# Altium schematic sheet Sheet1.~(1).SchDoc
size A
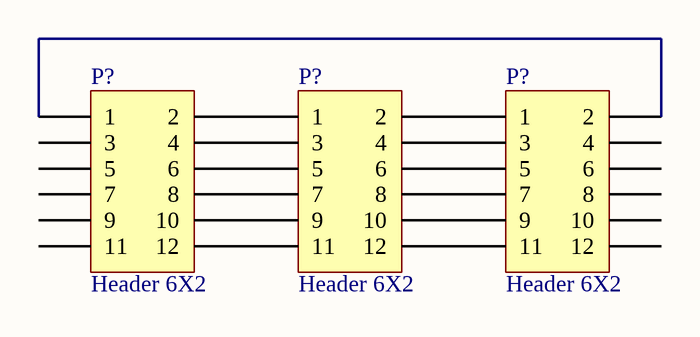
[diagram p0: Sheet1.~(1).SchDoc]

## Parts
(Parts that share a designator on the sheet are numbered #1, #2 ... from top to bottom, then left to right.)
P?#1  Header 6X2  [HDR2X6]
P?#2  Header 6X2  [HDR2X6]
P?#3  Header 6X2  [HDR2X6]

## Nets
NetP?#1_1: P?#1.1 P?#3.2
NetP?#1_2: P?#1.2 P?#2.1
NetP?#1_4: P?#1.4 P?#2.3
NetP?#1_6: P?#1.6 P?#2.5
NetP?#1_8: P?#1.8 P?#2.7
NetP?#1_10: P?#1.10 P?#2.9
NetP?#1_12: P?#1.12 P?#2.11
NetP?#2_2: P?#2.2 P?#3.1
NetP?#2_4: P?#2.4 P?#3.3
NetP?#2_6: P?#2.6 P?#3.5
NetP?#2_8: P?#2.8 P?#3.7
NetP?#2_10: P?#2.10 P?#3.9
NetP?#2_12: P?#2.12 P?#3.11

Not connected (* = marked no-connect by the designer): P?#1 3 5 7 9 11; P?#3 4 6 8 10 12

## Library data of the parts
P?#1-P?#3 = Header 6X2: Header, 6-Pin, Dual row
